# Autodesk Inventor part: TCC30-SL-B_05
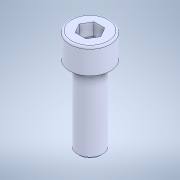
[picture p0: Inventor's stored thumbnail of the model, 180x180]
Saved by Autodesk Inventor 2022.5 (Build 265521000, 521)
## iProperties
Created: 2023-09
Part Number: TCC30-SL-B_05
Material: 一般
Document SubType Name: Modeling
Designer: ImaoCorp
Density: 1 g/cm^3
Appearance: 既定
Author: ImaoCorp
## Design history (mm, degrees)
feature "TCC30-SL-B_05"
node "ソリッド1"
